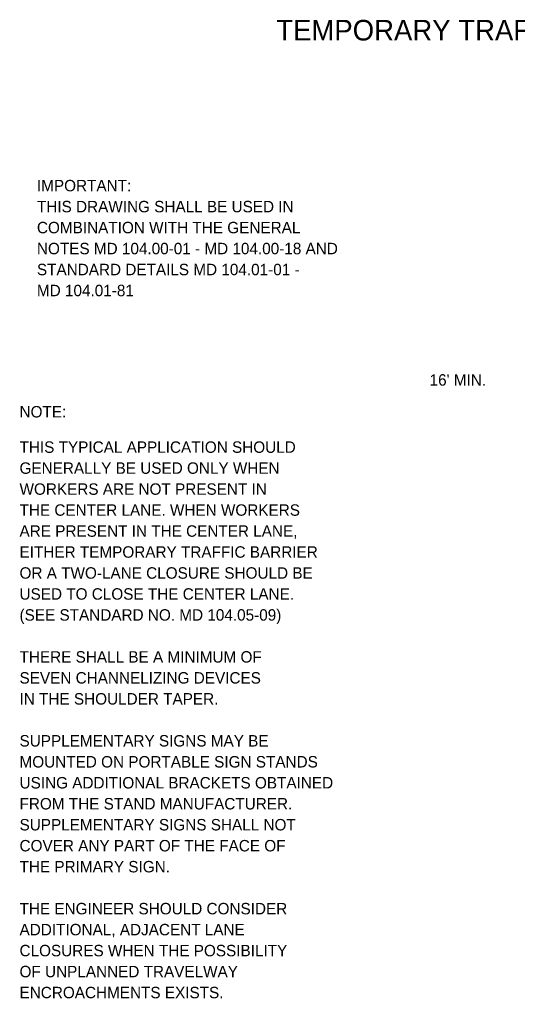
# Model space of a CAD drawing. Extents: x 1531.4 to 1538.58, y 1529.59 to 1539.33.
# Drawn here: x 1531.4 to 1534.01, y 1534.2 to 1539.33 of the extents above; entities that cross this region are included whole.
import ezdxf

# ---------------------------------------------------------------- set-up
doc = ezdxf.new("R2010")
doc.units = 0
doc.layers.add('DETL-NOTE', color=7, linetype='Continuous')
doc.layers.add('DETL-TITL', color=7, linetype='Continuous')

msp = doc.modelspace()

# ---------------------------------------------------------------- texts
at = {"layer": 'DETL-NOTE'}
for s, p in [('IMPORTANT:', (1531.4872, 1538.434)), ('THIS DRAWING SHALL BE USED IN', (1531.4872, 1538.324)), ('COMBINATION WITH THE GENERAL', (1531.4872, 1538.214)), ('NOTES MD 104.00-01 - MD 104.00-18 AND', (1531.4872, 1538.104)), ('STANDARD DETAILS MD 104.01-01 -', (1531.4872, 1537.994)), ('MD 104.01-81', (1531.4872, 1537.884)), ("16' MIN.", (1533.5471, 1537.415)), ('NOTE:', (1531.3959, 1537.2482)), ('THIS TYPICAL APPLICATION SHOULD ', (1531.3959, 1537.0628)), ('GENERALLY BE USED ONLY WHEN ', (1531.3959, 1536.9528)), ('WORKERS ARE NOT PRESENT IN ', (1531.3959, 1536.8428)), ('THE CENTER LANE. WHEN WORKERS ', (1531.3959, 1536.7328)), ('ARE PRESENT IN THE CENTER LANE, ', (1531.3959, 1536.6228)), ('EITHER TEMPORARY TRAFFIC BARRIER ', (1531.3959, 1536.5128)), ('OR A TWO-LANE CLOSURE SHOULD BE', (1531.3959, 1536.4028)), ('USED TO CLOSE THE CENTER LANE.', (1531.3959, 1536.2928)), ('(SEE STANDARD NO. MD 104.05-09)', (1531.3959, 1536.1828)), ('THERE SHALL BE A MINIMUM OF ', (1531.3959, 1535.9628)), ('SEVEN CHANNELIZING DEVICES ', (1531.3959, 1535.8528)), ('IN THE SHOULDER TAPER.', (1531.3959, 1535.7428)), ('SUPPLEMENTARY SIGNS MAY BE ', (1531.3959, 1535.5228)), ('MOUNTED ON PORTABLE SIGN STANDS ', (1531.3959, 1535.4128)), ('USING ADDITIONAL BRACKETS OBTAINED ', (1531.3959, 1535.3028)), ('FROM THE STAND MANUFACTURER. ', (1531.3959, 1535.1928)), ('SUPPLEMENTARY SIGNS SHALL NOT ', (1531.3959, 1535.0828)), ('COVER ANY PART OF THE FACE OF ', (1531.3959, 1534.9728)), ('THE PRIMARY SIGN.', (1531.3959, 1534.8628)), ('THE ENGINEER SHOULD CONSIDER', (1531.3959, 1534.6428)), ('ADDITIONAL, ADJACENT LANE', (1531.3959, 1534.5328)), ('CLOSURES WHEN THE POSSIBILITY', (1531.3959, 1534.4228)), ('OF UNPLANNED TRAVELWAY', (1531.3959, 1534.3128)), ('ENCROACHMENTS EXISTS.', (1531.3959, 1534.2028))]:
    msp.add_text(s, height=0.06, dxfattribs=at).set_placement(p)
at = {"layer": 'DETL-TITL'}
msp.add_text('TEMPORARY TRAFFIC CONTROL TYPICAL APPLICATION', height=0.108, dxfattribs=at).set_placement((1532.7424, 1539.225))

doc.saveas('drawing.dxf')
